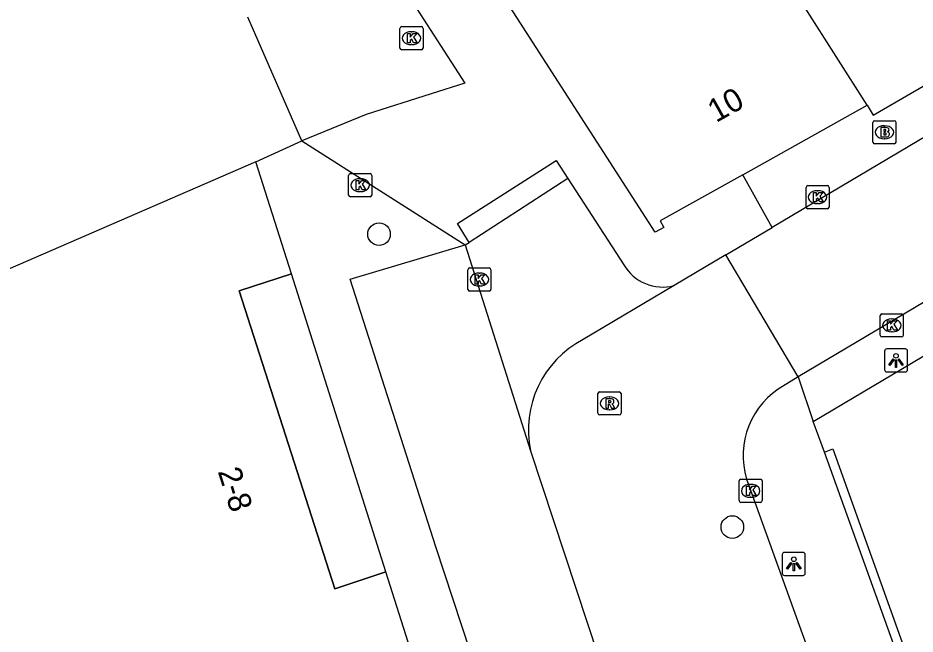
# Model space of a CAD drawing. Extents: x 159503 to 160347, y 382525 to 383272.
# Drawn here: x 159552.91 to 159591.78, y 382958.63 to 382985.33 of the extents above; entities that cross this region are included whole.
import ezdxf

# ---------------------------------------------------------------- set-up
doc = ezdxf.new("R2010")
doc.units = 0
for name, color, linetype in [('IMGEO_Boom', 7, 'Continuous'), ('IMGEO_Brandkraan', 7, 'Continuous'), ('IMGEO_Kolk', 7, 'Continuous'), ('IMGEO_Lichtpunt', 7, 'Continuous'), ('IMGEO_Pand', 7, 'Continuous'), ('IMGEO_Pand_nummerreeks', 7, 'Continuous'), ('IMGEO_Pand_overbouw', 7, 'Continuous'), ('IMGEO_Rijbaan_lokaal_open', 7, 'Continuous'), ('IMGEO_Rioolput', 7, 'Continuous'), ('IMGEO_Voetpad_open', 7, 'Continuous')]:
    doc.layers.add(name, color=color, linetype=linetype)

msp = doc.modelspace()

# ---------------------------------------------------------------- linework, layer by layer
at = {"layer": 'IMGEO_Boom'}
for centre in [(159568.554, 382975.96), (159583.86, 382963.269)]:
    msp.add_circle(centre, 0.489, dxfattribs=at)
at = {"layer": 'IMGEO_Brandkraan'}
for p, q in [((159590.024, 382980.88), (159590.876, 382980.88)), ((159589.949, 382979.954), (159589.949, 382980.806)), ((159590.437, 382980.66), (159590.462, 382980.66)), ((159590.95, 382980.806), (159590.95, 382979.954)), ((159590.46, 382980.1), (159590.435, 382980.1)), ((159590.876, 382979.88), (159590.024, 382979.88))]:
    msp.add_line(p, q, dxfattribs=at)
for points in [[(159590.024, 382980.88), (159590.876, 382980.88)], [(159589.949, 382979.954), (159589.949, 382980.806)], [(159590.297, 382980.58), (159590.297, 382980.18), (159590.51, 382980.18)], [(159590.528, 382980.58), (159590.297, 382980.58)], [(159590.476, 382980.499), (159590.422, 382980.499), (159590.422, 382980.423)], [(159590.95, 382980.806), (159590.95, 382979.954)], [(159590.422, 382980.423), (159590.475, 382980.423)], [(159590.484, 382980.347), (159590.422, 382980.347), (159590.422, 382980.266)], [(159590.422, 382980.266), (159590.484, 382980.266)], [(159590.876, 382979.88), (159590.024, 382979.88)]]:
    msp.add_lwpolyline(points, dxfattribs=at)
for centre, radius, start, end in [((159590.026, 382980.804), 0.0765, 91.552, 178.448), ((159590.026, 382980.804), 0.0765, 91.552, 178.448), ((159590.874, 382980.804), 0.0765, 1.552, 88.448), ((159590.874, 382980.804), 0.0765, 1.552, 88.448), ((159590.477, 382980.461), 0.0379, 267.8285, 90.9355), ((159590.532, 382980.435), 0.145, 59.4692, 91.5367), ((159590.557, 382980.482), 0.0922, 285.5137, 58.1501), ((159590.485, 382980.306), 0.0404, 269.8759, 90.5077), ((159590.516, 382980.431), 0.251, 268.6676, 293.5347), ((159590.562, 382980.29), 0.105, 301.3115, 78.989), ((159590.026, 382979.956), 0.0765, 181.552, 268.448), ((159590.026, 382979.956), 0.0765, 181.552, 268.448), ((159590.874, 382979.956), 0.0765, 271.552, 358.448), ((159590.874, 382979.956), 0.0765, 271.552, 358.448)]:
    msp.add_arc(centre, radius, start, end, dxfattribs=at)
for centre, major_axis, ratio, start_param, end_param in [((159590.436, 382980.38), (-0.387, 0.002), 0.722429, 4.712389, 7.853982), ((159590.461, 382980.38), (-0.39, 0.002), 0.717154, 1.570796, 4.712389)]:
    msp.add_ellipse(centre, major_axis=major_axis, ratio=ratio, start_param=start_param, end_param=end_param, dxfattribs=at)
at = {"layer": 'IMGEO_Kolk'}
for p, q in [((159569.461, 382984.029), (159569.461, 382984.881)), ((159569.536, 382984.955), (159570.388, 382984.955)), ((159569.949, 382984.735), (159569.974, 382984.735)), ((159570.462, 382984.881), (159570.462, 382984.029)), ((159570.388, 382983.955), (159569.536, 382983.955)), ((159569.972, 382984.175), (159569.947, 382984.175)), ((159567.236, 382977.659), (159567.236, 382978.511)), ((159567.311, 382978.585), (159568.163, 382978.585)), ((159568.237, 382978.511), (159568.237, 382977.659)), ((159567.724, 382978.365), (159567.749, 382978.365)), ((159567.747, 382977.805), (159567.722, 382977.805)), ((159587.052, 382977.138), (159587.052, 382977.99)), ((159587.127, 382978.064), (159587.979, 382978.064)), ((159587.54, 382977.844), (159587.565, 382977.844)), ((159588.053, 382977.99), (159588.053, 382977.138)), ((159568.163, 382977.585), (159567.311, 382977.585)), ((159587.979, 382977.064), (159587.127, 382977.064)), ((159587.563, 382977.284), (159587.538, 382977.284)), ((159572.402, 382973.57), (159572.402, 382974.422)), ((159572.477, 382974.496), (159573.329, 382974.496)), ((159572.89, 382974.276), (159572.915, 382974.276)), ((159573.403, 382974.422), (159573.403, 382973.57)), ((159573.329, 382973.496), (159572.477, 382973.496)), ((159572.913, 382973.716), (159572.888, 382973.716)), ((159590.267, 382971.582), (159590.267, 382972.434)), ((159590.342, 382972.508), (159591.194, 382972.508)), ((159590.755, 382972.288), (159590.78, 382972.288)), ((159591.268, 382972.434), (159591.268, 382971.582)), ((159591.194, 382971.508), (159590.342, 382971.508)), ((159590.778, 382971.728), (159590.753, 382971.728)), ((159584.228, 382965.339), (159585.08, 382965.339)), ((159584.153, 382964.413), (159584.153, 382965.265)), ((159584.641, 382965.119), (159584.666, 382965.119)), ((159585.154, 382965.265), (159585.154, 382964.413)), ((159584.664, 382964.559), (159584.639, 382964.559)), ((159585.08, 382964.339), (159584.228, 382964.339))]:
    msp.add_line(p, q, dxfattribs=at)
for points in [[(159569.461, 382984.029), (159569.461, 382984.881)], [(159569.536, 382984.955), (159570.388, 382984.955)], [(159570.462, 382984.881), (159570.462, 382984.029)], [(159569.782, 382984.655), (159569.905, 382984.655), (159569.905, 382984.504), (159570.035, 382984.655), (159570.199, 382984.655), (159570.053, 382984.504), (159570.206, 382984.255), (159570.054, 382984.255), (159569.969, 382984.419), (159569.905, 382984.352), (159569.905, 382984.255), (159569.782, 382984.255), (159569.782, 382984.655)], [(159570.388, 382983.955), (159569.536, 382983.955)], [(159567.236, 382977.659), (159567.236, 382978.511)], [(159567.311, 382978.585), (159568.163, 382978.585)], [(159568.237, 382978.511), (159568.237, 382977.659)], [(159567.557, 382978.285), (159567.68, 382978.285), (159567.68, 382978.134), (159567.81, 382978.285), (159567.974, 382978.285), (159567.828, 382978.134), (159567.981, 382977.885), (159567.829, 382977.885), (159567.744, 382978.049), (159567.68, 382977.982), (159567.68, 382977.885), (159567.557, 382977.885), (159567.557, 382978.285)], [(159587.052, 382977.138), (159587.052, 382977.99)], [(159587.127, 382978.064), (159587.979, 382978.064)], [(159587.373, 382977.764), (159587.496, 382977.764), (159587.496, 382977.613), (159587.626, 382977.764), (159587.79, 382977.764), (159587.644, 382977.613), (159587.797, 382977.364), (159587.645, 382977.364), (159587.56, 382977.528), (159587.496, 382977.461), (159587.496, 382977.364), (159587.373, 382977.364), (159587.373, 382977.764)], [(159588.053, 382977.99), (159588.053, 382977.138)], [(159568.163, 382977.585), (159567.311, 382977.585)], [(159587.979, 382977.064), (159587.127, 382977.064)], [(159572.402, 382973.57), (159572.402, 382974.422)], [(159572.477, 382974.496), (159573.329, 382974.496)], [(159573.403, 382974.422), (159573.403, 382973.57)], [(159572.723, 382974.196), (159572.846, 382974.196), (159572.846, 382974.045), (159572.976, 382974.196), (159573.14, 382974.196), (159572.994, 382974.045), (159573.147, 382973.796), (159572.995, 382973.796), (159572.91, 382973.96), (159572.846, 382973.893), (159572.846, 382973.796), (159572.723, 382973.796), (159572.723, 382974.196)], [(159573.329, 382973.496), (159572.477, 382973.496)], [(159590.267, 382971.582), (159590.267, 382972.434)], [(159590.342, 382972.508), (159591.194, 382972.508)], [(159591.268, 382972.434), (159591.268, 382971.582)], [(159590.588, 382972.208), (159590.711, 382972.208), (159590.711, 382972.057), (159590.841, 382972.208), (159591.005, 382972.208), (159590.859, 382972.057), (159591.012, 382971.808), (159590.86, 382971.808), (159590.775, 382971.972), (159590.711, 382971.905), (159590.711, 382971.808), (159590.588, 382971.808), (159590.588, 382972.208)], [(159591.194, 382971.508), (159590.342, 382971.508)], [(159584.228, 382965.339), (159585.08, 382965.339)], [(159584.153, 382964.413), (159584.153, 382965.265)], [(159584.474, 382965.039), (159584.597, 382965.039), (159584.597, 382964.888), (159584.727, 382965.039), (159584.891, 382965.039), (159584.745, 382964.888), (159584.898, 382964.639), (159584.746, 382964.639), (159584.661, 382964.803), (159584.597, 382964.736), (159584.597, 382964.639), (159584.474, 382964.639), (159584.474, 382965.039)], [(159585.154, 382965.265), (159585.154, 382964.413)], [(159585.08, 382964.339), (159584.228, 382964.339)]]:
    msp.add_lwpolyline(points, dxfattribs=at)
for centre, start, end in [((159569.538, 382984.879), 91.552, 178.448), ((159569.538, 382984.879), 91.552, 178.448), ((159570.386, 382984.879), 1.552, 88.448), ((159570.386, 382984.879), 1.552, 88.448), ((159569.538, 382984.031), 181.552, 268.448), ((159569.538, 382984.031), 181.552, 268.448), ((159570.386, 382984.031), 271.552, 358.448), ((159570.386, 382984.031), 271.552, 358.448), ((159567.313, 382978.509), 91.552, 178.448), ((159567.313, 382978.509), 91.552, 178.448), ((159568.161, 382978.509), 1.552, 88.448), ((159568.161, 382978.509), 1.552, 88.448), ((159587.129, 382977.988), 91.552, 178.448), ((159587.129, 382977.988), 91.552, 178.448), ((159587.977, 382977.988), 1.552, 88.448), ((159587.977, 382977.988), 1.552, 88.448), ((159567.313, 382977.661), 181.552, 268.448), ((159567.313, 382977.661), 181.552, 268.448), ((159568.161, 382977.661), 271.552, 358.448), ((159568.161, 382977.661), 271.552, 358.448), ((159587.129, 382977.14), 181.552, 268.448), ((159587.129, 382977.14), 181.552, 268.448), ((159587.977, 382977.14), 271.552, 358.448), ((159587.977, 382977.14), 271.552, 358.448), ((159572.479, 382974.42), 91.552, 178.448), ((159572.479, 382974.42), 91.552, 178.448), ((159573.327, 382974.42), 1.552, 88.448), ((159573.327, 382974.42), 1.552, 88.448), ((159572.479, 382973.572), 181.552, 268.448), ((159572.479, 382973.572), 181.552, 268.448), ((159573.327, 382973.572), 271.552, 358.448), ((159573.327, 382973.572), 271.552, 358.448), ((159590.344, 382972.432), 91.552, 178.448), ((159590.344, 382972.432), 91.552, 178.448), ((159591.192, 382972.432), 1.552, 88.448), ((159591.192, 382972.432), 1.552, 88.448), ((159590.344, 382971.584), 181.552, 268.448), ((159590.344, 382971.584), 181.552, 268.448), ((159591.192, 382971.584), 271.552, 358.448), ((159591.192, 382971.584), 271.552, 358.448), ((159584.23, 382965.263), 91.552, 178.448), ((159584.23, 382965.263), 91.552, 178.448), ((159585.078, 382965.263), 1.552, 88.448), ((159585.078, 382965.263), 1.552, 88.448), ((159584.23, 382964.415), 181.552, 268.448), ((159584.23, 382964.415), 181.552, 268.448), ((159585.078, 382964.415), 271.552, 358.448), ((159585.078, 382964.415), 271.552, 358.448)]:
    msp.add_arc(centre, 0.0765, start, end, dxfattribs=at)
for centre, major_axis, ratio, start_param, end_param in [((159569.948, 382984.455), (-0.387, 0.002), 0.722429, 4.712389, 7.853982), ((159569.973, 382984.455), (-0.39, 0.002), 0.717154, 1.570796, 4.712389), ((159567.723, 382978.085), (-0.387, 0.002), 0.722429, 4.712389, 7.853982), ((159567.748, 382978.085), (-0.39, 0.002), 0.717154, 1.570796, 4.712389), ((159587.539, 382977.564), (-0.387, 0.002), 0.722429, 4.712389, 7.853982), ((159587.564, 382977.564), (-0.39, 0.002), 0.717154, 1.570796, 4.712389), ((159572.889, 382973.996), (-0.387, 0.002), 0.722429, 4.712389, 7.853982), ((159572.914, 382973.996), (-0.39, 0.002), 0.717154, 1.570796, 4.712389), ((159590.754, 382972.008), (-0.387, 0.002), 0.722429, 4.712389, 7.853982), ((159590.779, 382972.008), (-0.39, 0.002), 0.717154, 1.570796, 4.712389), ((159584.64, 382964.839), (-0.387, 0.002), 0.722429, 4.712389, 7.853982), ((159584.665, 382964.839), (-0.39, 0.002), 0.717154, 1.570796, 4.712389)]:
    msp.add_ellipse(centre, major_axis=major_axis, ratio=ratio, start_param=start_param, end_param=end_param, dxfattribs=at)
at = {"layer": 'IMGEO_Lichtpunt'}
for p, q in [((159590.453, 382970.893), (159590.453, 382970.086)), ((159590.453, 382970.893), (159590.453, 382970.086)), ((159591.355, 382970.988), (159590.547, 382970.988)), ((159591.355, 382970.988), (159590.547, 382970.988)), ((159591.449, 382970.086), (159591.449, 382970.893)), ((159591.449, 382970.086), (159591.449, 382970.893)), ((159590.547, 382969.992), (159591.355, 382969.992)), ((159590.547, 382969.992), (159591.355, 382969.992)), ((159586.024, 382962.075), (159586.024, 382961.268)), ((159586.024, 382962.075), (159586.024, 382961.268)), ((159586.926, 382962.17), (159586.118, 382962.17)), ((159586.926, 382962.17), (159586.118, 382962.17)), ((159587.02, 382961.268), (159587.02, 382962.075)), ((159587.02, 382961.268), (159587.02, 382962.075)), ((159586.118, 382961.174), (159586.926, 382961.174)), ((159586.118, 382961.174), (159586.926, 382961.174))]:
    msp.add_line(p, q, dxfattribs=at)
for points in [[(159590.827, 382970.557), (159590.866, 382970.529), (159590.678, 382970.267), (159590.64, 382970.294), (159590.827, 382970.557)], [(159590.929, 382970.509), (159590.976, 382970.509), (159590.976, 382970.187), (159590.929, 382970.187), (159590.929, 382970.509)], [(159591.039, 382970.529), (159591.077, 382970.556), (159591.264, 382970.294), (159591.225, 382970.266), (159591.039, 382970.529)], [(159586.398, 382961.739), (159586.437, 382961.711), (159586.249, 382961.449), (159586.211, 382961.476), (159586.398, 382961.739)], [(159586.5, 382961.691), (159586.547, 382961.691), (159586.547, 382961.369), (159586.5, 382961.369), (159586.5, 382961.691)], [(159586.61, 382961.711), (159586.648, 382961.738), (159586.835, 382961.476), (159586.796, 382961.448), (159586.61, 382961.711)]]:
    msp.add_lwpolyline(points, dxfattribs=at)
for centre in [(159590.952, 382970.691), (159586.523, 382961.873)]:
    msp.add_circle(centre, 0.0994, dxfattribs=at)
for centre, start, end in [((159590.547, 382970.893), 90, 180), ((159590.547, 382970.893), 90, 180), ((159591.355, 382970.893), 0, 90), ((159591.355, 382970.893), 0, 90), ((159590.547, 382970.086), 180, 270), ((159590.547, 382970.086), 180, 270), ((159591.355, 382970.086), 270, 0), ((159591.355, 382970.086), 270, 360), ((159586.118, 382962.075), 90, 180), ((159586.118, 382962.075), 90, 180), ((159586.926, 382962.075), 0, 90), ((159586.926, 382962.075), 0, 90), ((159586.118, 382961.268), 180, 270), ((159586.118, 382961.268), 180, 270), ((159586.926, 382961.268), 270, 0), ((159586.926, 382961.268), 270, 360)]:
    msp.add_arc(centre, 0.0946, start, end, dxfattribs=at)
at = {"layer": 'IMGEO_Pand'}
for points in [[(159589.699, 382981.552), (159587.016, 382985.773), (159580.673, 382995.756), (159575.025, 383004.447), (159565.97, 382998.562)], [(159584.314, 382978.537), (159580.736, 382976.534), (159580.891, 382976.254), (159580.524, 382976.049), (159571.589, 382989.915), (159565.97, 382998.562)], [(159565.208, 382980.005), (159562.875, 382985.371)], [(159587.366, 382967.842), (159616.76, 382985.295)], [(159584.314, 382978.537), (159589.699, 382981.552)], [(159563.21, 382979.1), (159565.208, 382980.005)], [(159563.21, 382979.1), (159538.52, 382968.383)], [(159564.758, 382974.237), (159563.21, 382979.1)], [(159568.852, 382961.323), (159566.639, 382960.597), (159562.49, 382973.512), (159564.758, 382974.237)], [(159587.852, 382966.52), (159587.366, 382967.842)], [(159587.852, 382966.52), (159588.22, 382966.653), (159594.075, 382950.274)], [(159571.265, 382953.723), (159568.852, 382961.323)]]:
    msp.add_lwpolyline(points, dxfattribs=at)
at = {"layer": 'IMGEO_Pand_overbouw'}
msp.add_lwpolyline([(159568.852, 382961.323), (159564.758, 382974.237), (159562.49, 382973.512), (159566.639, 382960.597)], close=True, dxfattribs=at)
at = {"layer": 'IMGEO_Rijbaan_lokaal_open'}
for points in [[(159724.205, 383058.665), (159687.242, 383036.582), (159585.591, 382976.257)], [(159719.236, 383048.422), (159586.71, 382969.778)], [(159576.731, 382978.377), (159572.457, 382975.603)], [(159576.731, 382978.377), (159579.153, 382974.634)], [(159583.575, 382975.061), (159585.591, 382976.257)], [(159572.292, 382975.496), (159572.457, 382975.603)], [(159572.292, 382975.496), (159575.122, 382966.572)], [(159583.575, 382975.061), (159581.339, 382973.734)], [(159586.71, 382969.778), (159583.575, 382975.061)], [(159581.339, 382973.734), (159577.394, 382971.393)], [(159586.71, 382969.778), (159585.847, 382969.246)], [(159575.122, 382966.572), (159582.001, 382945.695)], [(159584.573, 382965.063), (159592.904, 382941.945)]]:
    msp.add_lwpolyline(points, dxfattribs=at)
for centre, radius, start, end in [((159580.845, 382975.638), 1.968, 210.6988, 284.5462), ((159579.43, 382967.488), 4.404, 117.5365, 191.9972), ((159587.833, 382966.356), 3.507, 124.4882, 201.6339)]:
    msp.add_arc(centre, radius, start, end, dxfattribs=at)
at = {"layer": 'IMGEO_Rioolput'}
for p, q in [((159578.036, 382968.201), (159578.036, 382969.053)), ((159578.111, 382969.127), (159578.963, 382969.127)), ((159578.524, 382968.907), (159578.549, 382968.907)), ((159579.037, 382969.053), (159579.037, 382968.201)), ((159578.963, 382968.127), (159578.111, 382968.127)), ((159578.547, 382968.347), (159578.522, 382968.347))]:
    msp.add_line(p, q, dxfattribs=at)
for points in [[(159578.036, 382968.201), (159578.036, 382969.053)], [(159578.111, 382969.127), (159578.963, 382969.127)], [(159578.625, 382968.825), (159578.373, 382968.827), (159578.373, 382968.427)], [(159579.037, 382969.053), (159579.037, 382968.201)], [(159578.373, 382968.427), (159578.497, 382968.427), (159578.497, 382968.589), (159578.508, 382968.589)], [(159578.551, 382968.746), (159578.497, 382968.746), (159578.497, 382968.665)], [(159578.497, 382968.665), (159578.549, 382968.665)], [(159578.555, 382968.56), (159578.626, 382968.427), (159578.766, 382968.427), (159578.701, 382968.553)], [(159578.963, 382968.127), (159578.111, 382968.127)]]:
    msp.add_lwpolyline(points, dxfattribs=at)
for centre, radius, start, end in [((159578.113, 382969.051), 0.0765, 91.552, 178.448), ((159578.113, 382969.051), 0.0765, 91.552, 178.448), ((159578.624, 382968.715), 0.109, 350.3612, 89.416), ((159578.961, 382969.051), 0.0765, 1.552, 88.448), ((159578.961, 382969.051), 0.0765, 1.552, 88.448), ((159578.507, 382968.536), 0.0533, 26.0293, 88.6989), ((159578.533, 382968.854), 0.19, 274.7715, 282.9687), ((159578.557, 382968.65), 0.0964, 77.0061, 93.1865), ((159578.571, 382968.707), 0.0378, 276.6634, 79.6772), ((159578.622, 382968.715), 0.112, 277.5842, 350.9817), ((159578.606, 382968.5), 0.108, 29.5134, 73.7905), ((159578.113, 382968.203), 0.0765, 181.552, 268.448), ((159578.113, 382968.203), 0.0765, 181.552, 268.448), ((159578.961, 382968.203), 0.0765, 271.552, 358.448), ((159578.961, 382968.203), 0.0765, 271.552, 358.448)]:
    msp.add_arc(centre, radius, start, end, dxfattribs=at)
for centre, major_axis, ratio, start_param, end_param in [((159578.523, 382968.627), (-0.387, 0.002), 0.722429, 4.712389, 7.853982), ((159578.548, 382968.627), (-0.39, 0.002), 0.717154, 1.570796, 4.712389)]:
    msp.add_ellipse(centre, major_axis=major_axis, ratio=ratio, start_param=start_param, end_param=end_param, dxfattribs=at)
at = {"layer": 'IMGEO_Voetpad_open'}
for points in [[(159568.247, 382988.759), (159572.27, 382982.509), (159570.807, 382982.041), (159567.995, 382981.142), (159565.208, 382980.005)], [(159589.699, 382981.552), (159589.966, 382981.122), (159601.638, 382987.915), (159601.959, 382988.106)], [(159565.208, 382980.005), (159572.292, 382975.496)], [(159572.457, 382975.603), (159571.96, 382976.42), (159576.224, 382979.161), (159576.731, 382978.377)], [(159585.591, 382976.257), (159584.314, 382978.537)], [(159577.04, 382944.103), (159571.02, 382962.408), (159567.304, 382974.008), (159572.292, 382975.496)], [(159568.852, 382961.323), (159564.758, 382974.237)], [(159586.71, 382969.778), (159587.366, 382967.842)], [(159595.17, 382946.154), (159587.852, 382966.52)]]:
    msp.add_lwpolyline(points, dxfattribs=at)

# ---------------------------------------------------------------- texts
at = {"layer": 'IMGEO_Pand_nummerreeks'}
for s, rotation, p in [('10', 29.2426, (159583.155, 382980.776)), ('2-8', 287.8098, (159561.56, 382965.683))]:
    msp.add_text(s, height=1, rotation=rotation, dxfattribs=at).set_placement(p)

doc.saveas('drawing.dxf')
